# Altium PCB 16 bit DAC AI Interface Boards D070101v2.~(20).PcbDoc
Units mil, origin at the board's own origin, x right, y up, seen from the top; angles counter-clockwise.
Board outline 2600 x 10000 mil, 4 copper layers (Top Layer, InternalPlane1, InternalPlane2, Bottom Layer); 6 components, 34 nets, 183 pads, 15 vias.
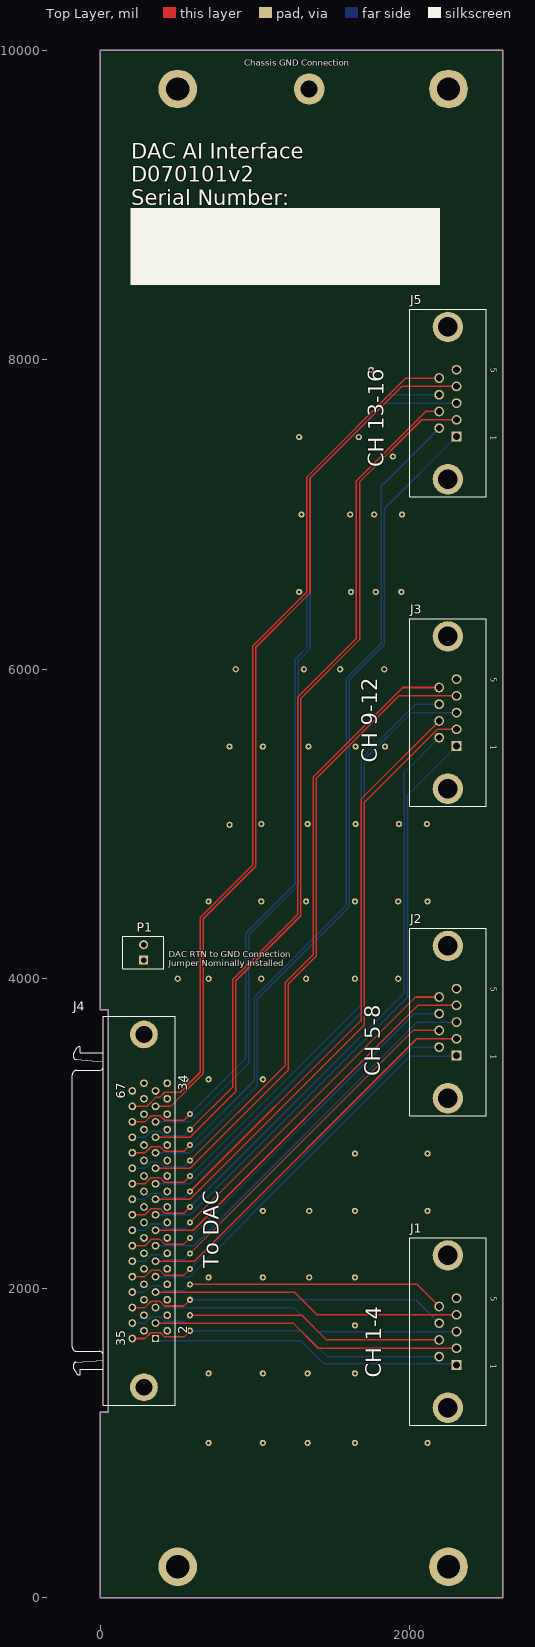
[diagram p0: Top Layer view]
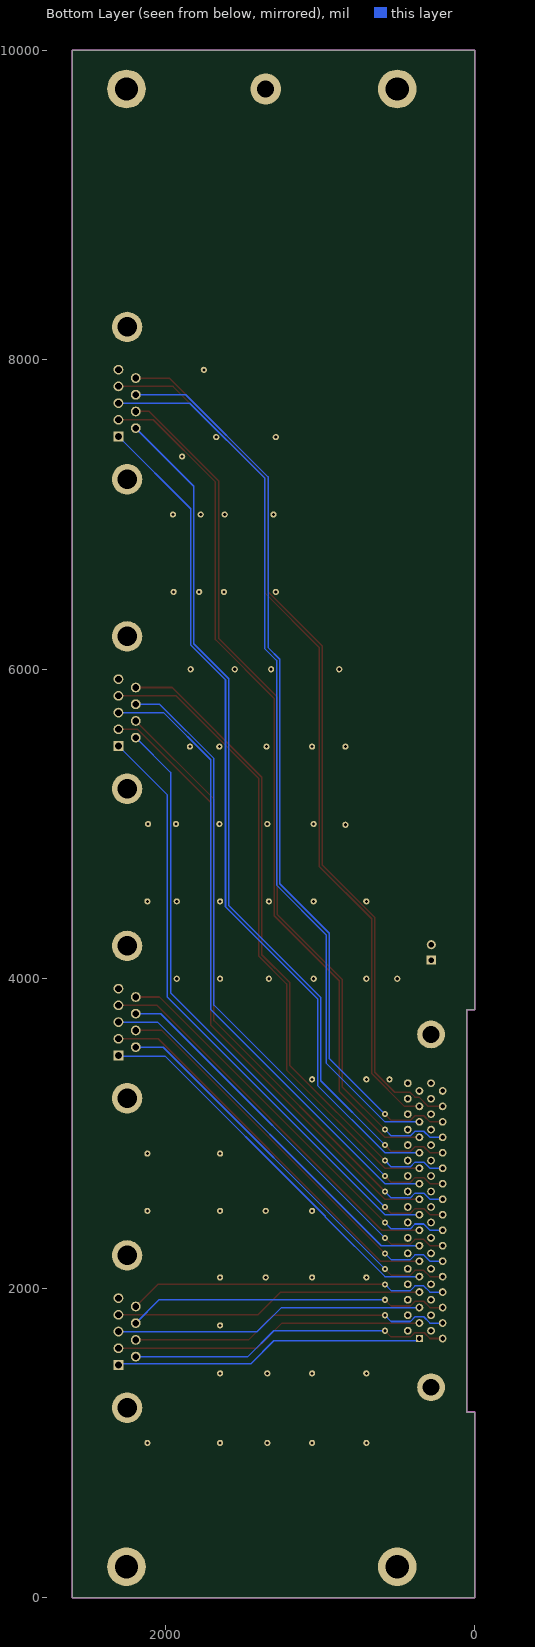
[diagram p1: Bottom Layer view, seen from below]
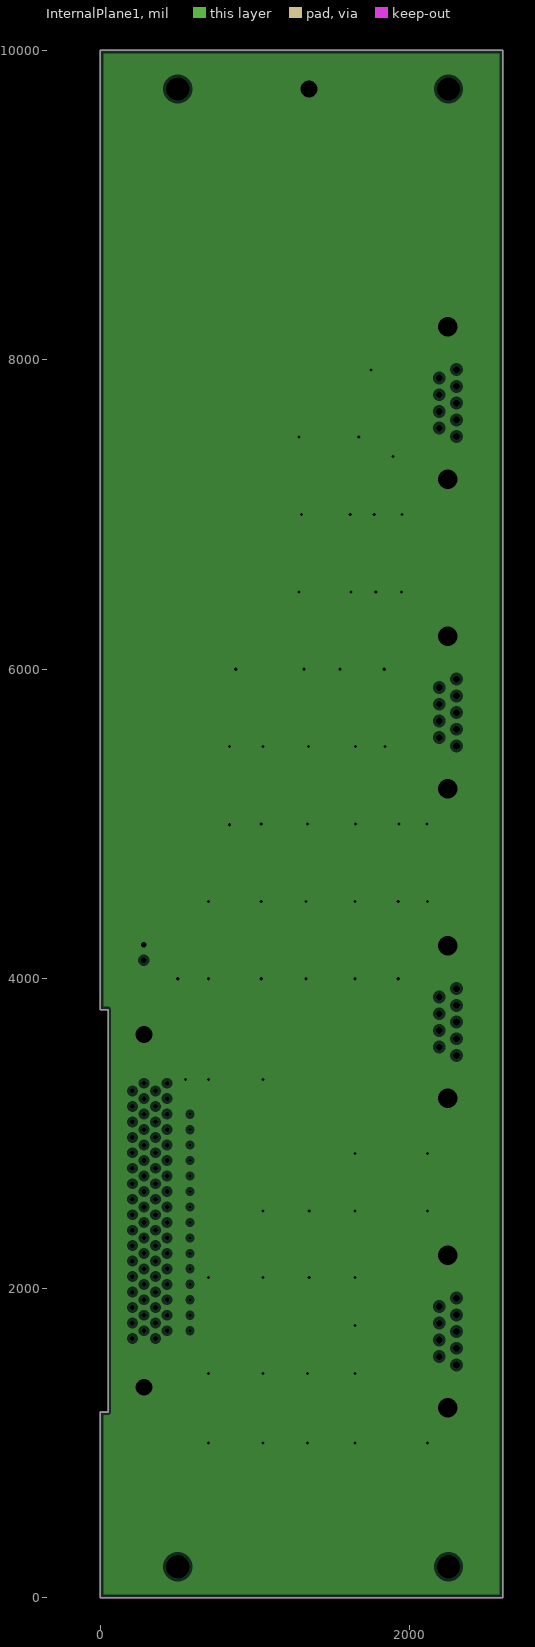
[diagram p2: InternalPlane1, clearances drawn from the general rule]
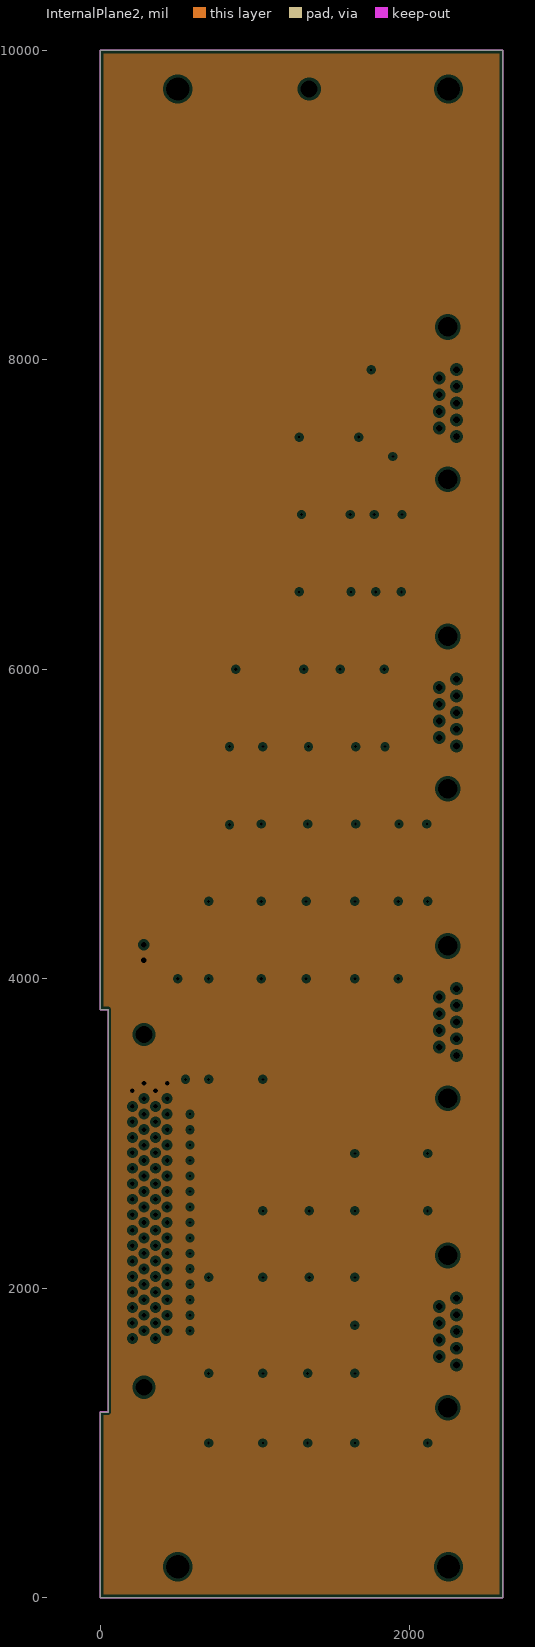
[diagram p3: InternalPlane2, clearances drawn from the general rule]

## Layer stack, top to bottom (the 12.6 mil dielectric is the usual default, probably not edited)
Top Solder: solder mask 0.4, Solder Resist, Dk 3.5
Top Layer: signal copper 1.4
Dielectric1: core 12.6, FR-4, Dk 4.8
InternalPlane1: plane copper 1.4, net GND
Dielectric2: prepreg 12.6, FR-4, Dk 4.8
InternalPlane2: plane copper 1.4, net INPUTRTN
Dielectric3: core 12.6, FR-4, Dk 4.8
Bottom Layer: signal copper 1.4
Bottom Solder: solder mask 0.4, Solder Resist, Dk 3.5

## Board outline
0,0 0,1200 50,1200 50,3800 0,3800 0,10000 2600,10000 2600,0

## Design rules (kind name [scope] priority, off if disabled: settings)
Clearance [All] p1: gap=10 ignorepadtopadclearanceinfootprint=FALSE except(0: Arc-Hole Track-Hole SMDPad-Hole THPad-Hole Via-Hole Fill-Hole Poly-Hole Region-Hole Text-Hole)
FabricationTestPointUsage TestPointUsage [All] p1: valid=0 allowmultiple=FALSE
FabricationTestpoint Testpoint [All] p1: side=3 testpointundercomponent=TRUE minsize=40 maxsize=100 preferedsize=60 minholesize=0 maxholesize=40 preferedholesize=32 testpointgrid=1 allowsidetop=TRUE allowsidebottom=TRUE usegrid=TRUE gridtolerance=0.01
HoleSize [All] p1: absolutevalues=TRUE maxlimit=200 minlimit=1 maxpercent=80.000 minpercent=20.000
PlaneClearance [All] p1: clearance=20
PlaneConnect [All] p1: planeconnectstyle=Relief reliefexpansion=20 reliefentries=4 reliefconductorwidth=10 reliefairgap=10
PolygonConnect [All] p1: connectstyle=Relief reliefconductorwidth=10 reliefentries=4 polygonreliefangle="90 Angle" airgapwidth=10
RoutingVias [All] p1: holewidth=20 width=40 viastyle="Through Hole" minholewidth=20 minwidth=40 maxholewidth=28 maxwidth=50
SolderMaskExpansion [All] p1: expansion=4
Width [All] p1: maxlimit=100 minlimit=10 preferedwidth=10
25 further rules are at their usual default settings.

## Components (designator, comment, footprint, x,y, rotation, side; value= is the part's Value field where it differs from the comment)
J1 "D9F" D9F 2246,1720 r270 top
J2 "D9F" D9F 2246,3720 r270 top
J3 "D9F" D9F 2246,5720 r270 top
J4 "787082-7" 787082-7 20,2500 r90 top
J5 "D9F" D9F 2246,7720 r270 top
P1 "Header 2" HDR1X2 280,4120 r90 top

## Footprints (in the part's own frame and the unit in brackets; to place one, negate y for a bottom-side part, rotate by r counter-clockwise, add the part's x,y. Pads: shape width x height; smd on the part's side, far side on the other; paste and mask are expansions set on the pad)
787082-7 [mm] "Connector; D Subminiature 050 Series; 68 Position; Right Angle"
  rect 1.143x1.143 hole 0.762: 1(-20.955,-8.555)
  round 1.27 hole 0.762: 2(-19.685,-10.46) 3(-18.415,-8.555) 4(-17.145,-10.46) 5(-15.875,-8.555) 6(-14.605,-10.46) 7(-13.335,-8.555) 8(-12.065,-10.46) 9(-10.795,-8.555) 10(-9.525,-10.46) 11(-8.255,-8.555) 12(-6.985,-10.46) 13(-5.715,-8.555) 14(-4.445,-10.46) 15(-3.175,-8.555) 16(-1.905,-10.46) 17(-0.635,-8.555) 18(0.635,-10.46) 19(1.905,-8.555) 20(3.175,-10.46) 21(4.445,-8.555) 22(5.715,-10.46) 23(6.985,-8.555) 24(8.255,-10.46) 25(9.525,-8.555) 26(10.795,-10.46) 27(12.065,-8.555) 28(13.335,-10.46) 29(14.605,-8.555) 30(15.875,-10.46) 31(17.145,-8.555) 32(18.415,-10.46) 33(19.685,-8.555) 34(20.955,-10.46) 35(-20.955,-4.745) 36(-19.685,-6.65) 37(-18.415,-4.745) 38(-17.145,-6.65) 39(-15.875,-4.745) 40(-14.605,-6.65) 41(-13.335,-4.745) 42(-12.065,-6.65) 43(-10.795,-4.745) 44(-9.525,-6.65) 45(-8.255,-4.745) 46(-6.985,-6.65) 47(-5.715,-4.745) 48(-4.445,-6.65) 49(-3.175,-4.745) 50(-1.905,-6.65) 51(-0.635,-4.745) 52(0.635,-6.65) 53(1.905,-4.745) 54(3.175,-6.65) 55(4.445,-4.745) 56(5.715,-6.65) 57(6.985,-4.745) 58(8.255,-6.65) 59(9.525,-4.745) 60(10.795,-6.65) 61(12.065,-4.745) 62(13.335,-6.65) 63(14.605,-4.745) 64(15.875,-6.65) 65(17.145,-4.745) 66(18.415,-6.65) 67(19.685,-4.745) 68(20.955,-6.65)
  round 4.55 hole 2.77: 69(-28.955,-6.65) 70(28.955,-6.65)
  silkscreen extent -31.95,-11.76 31.95,5.11, body extent -31.94,-11.8 31.94,5.07, height 9.49
D9F [mm]
  rect 1.6x1.6 hole 1.1: 1(5.486,1.422)
  round 1.6 hole 1.1: 2(2.743,1.422) 3(0.005,1.422) 4(-2.743,1.422) 5(-5.486,1.422) 6(4.115,-1.422) 7(1.372,-1.422) 8(-1.372,-1.422) 9(-4.115,-1.422)
  round 5 hole 3.2: 10(-12.497,0) 11(12.497,0)
  silkscreen extent -15.4,-6.3 15.4,6.3, body extent -15.4,-6.3 15.41,6.3, height 12.18
HDR1X2 [mm] "Connector; Header; 2 Position"
  rect 1.5x1.5 hole 0.9: 1(0,0)
  round 1.5 hole 0.9: 2(2.54,0)
  silkscreen extent -1.4,-3.3 3.94,3.43, body extent -1.19,-3.1 3.73,3.25, height 10.68

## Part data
J1 J2 J3 J5: "9 Position D-Sub Receptacle, Female Sockets Connector", Case/Package=Metal, Color=Black, Current Rating=6A, Flammability Rating="UL94 V-0", Manufacturer="TE Connectivity", Manufacturer Part Number=5747150-7, Max Operating Temperature=105°C, Max Supply Voltage (AC)=250V, Max Voltage Rating (DC)=250.25kV, Min Operating Temperature=-55°C, Package Quantity=17, Supplier Part Number 1=A34073-ND, Voltage Rating=125V
J4: library part "D68F 90deg", "68 Position D-Type Receptacle, Female Sockets Connector", Color=Black, Current Rating=1A, Flammability Rating="UL94 V-0", Manufacturer="TE Connectivity", Manufacturer Part Number=7870827, Max Operating Temperature=105°C, Min Operating Temperature=-55°C, Package Quantity=8, Supplier Part Number 1=A3321-ND, Voltage Rating=30V
P1: "Connector Header Through Hole 2 position 0.100\" (2.54mm)", Color=White, Contact Resistance=10mR, Current Rating=4A, Flammability Rating="UL94 V-0", Insulation Resistance=500GR, Manufacturer=Molex, Manufacturer Part Number=22-23-2021, Max Operating Temperature=75°C, Min Operating Temperature=0°C, Package Quantity=3000, Supplier Part Number 1=WM4200-ND, Voltage Rating=250V

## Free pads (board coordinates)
  round 200 hole 110: 0(1350,9750)
  round 250 hole 150: 0(2250,200) 1(2250,9750) 2(500,9750) 3(500,200)
  round 40 hole 20: 5(1645,1450) 6(2115,1000) 7(1645,1760) 8(1645,1000) 9(700,1450) 10(1050,2070) 11(1645,2070) 12(1050,1000) 13(700,1000) 14(1050,2500) 15(1645,2500) 16(2115,2870) 21(1050,3350) 22(1350,2500) 23(700,3350) 24(700,2070) 25(550,3350) 26(700,4000) 27(1040,4000) 28(1330,4000) 29(1645,4000) 30(1925,4000) 32(1645,2870) 36(1340,1000) 36(1340,1450) 36(1350,2070) 37(1040,4500) 38(1330,4500) 39(1645,4500) 40(1925,4500) 41(1930,5000) 42(1650,5000) 43(1340,5000) 44(1040,5000) 45(835,4995) 46(700,4500) 47(500,4000) 48(835,5500) 49(1050,5500) 50(1345,5500) 51(1650,5500) 52(1840,5500) 53(1835,6000) 54(1550,6000) 55(1315,6000) 56(875,6000) 57(1620,6500) 58(1780,6500) 59(1945,6500) 60(1285,6500) 61(1300,7000) 62(1615,7000) 63(1770,7000) 64(1950,7000) 65(1890,7375) 66(1670,7500) 67(1285,7500) 68(1750,7935) 69(2115,4500) 70(2110,5000) 71(2115,2500) 75(1050,1450)

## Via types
v1: diameter 40, hole 20, Top Layer to Bottom Layer, 15 vias

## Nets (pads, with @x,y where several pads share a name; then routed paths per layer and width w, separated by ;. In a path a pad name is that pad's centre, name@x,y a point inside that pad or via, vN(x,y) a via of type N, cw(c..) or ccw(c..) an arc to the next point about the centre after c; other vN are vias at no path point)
GND: J1.10 J1.11 J2.10 J2.11 J3.10 J3.11 J4.69 J4.70 J5.10 J5.11 P1.2 pad.0@1350,9750 pad.5 pad.6 pad.7 pad.8 pad.9 pad.10 pad.11 pad.12 pad.13 pad.14 pad.15 pad.16 pad.21 pad.22 pad.23 pad.24 pad.25 pad.26 pad.27 pad.28 pad.29 pad.30 pad.32 pad.36 pad.37 pad.38 pad.39 pad.40 pad.41 pad.42 pad.43 pad.44 pad.45 pad.46 pad.47 pad.48 pad.49 pad.50 pad.51 pad.52 pad.53 pad.54 pad.55 pad.56 pad.57 pad.58 pad.59 pad.60 pad.61 pad.62 pad.63 pad.64 pad.65 pad.66 pad.67 pad.68 pad.69 pad.70 pad.71 pad.75
INPUTN1: J1.6 J4.35 | length 2097.1
  Top Layer w10: J4.35 288.38,1675 325.88,1712.5 387.74,1712.5 415.24,1685 540,1685 v1(580,1725)
  Bottom Layer w10: v1(580,1725) 1298.39,1725 1465.39,1558 2187,1558 J1.6@2190,1555
INPUTN2: J1.7 J4.37 | length 2095.4
  Top Layer w10: v1(580,1825) 1302.39,1825 1461.39,1666 2188,1666 J1.7@2190,1664
  Bottom Layer w10: J4.37 288.38,1775 328.38,1815 385.24,1815 415.24,1785 540,1785 v1(580,1825)
INPUTN3: J1.8 J4.39 | length 2091.3
  Top Layer w10: J4.39 288.38,1875 328.38,1915 385.24,1915 415.24,1885 540,1885 v1(580,1925)
  Bottom Layer w10: v1(580,1925) 2039,1925 J1.8
INPUTN4: J1.9 J4.41 | length 2088
  Top Layer w10: v1(580,2025) 2047,2025 J1.9
  Bottom Layer w10: J4.41 288.38,1975 328.38,2015 385.24,2015 415.24,1985 540,1985 v1(580,2025)
INPUTN5: J2.6 J4.43 | length 2623.6
  Top Layer w10: J4.43 288.38,2075 328.38,2115 385.24,2115 415.24,2085 540,2085 v1(580,2125)
  Bottom Layer w10: v1(580,2125) 2013,3558 2187,3558 J2.6@2190,3555
INPUTN6: J2.7 J4.45 | length 2626.5
  Top Layer w10: v1(580,2225) 2021,3666 2188,3666 J2.7@2190,3664
  Bottom Layer w10: J4.45 288.38,2175 328.38,2215 385.24,2215 415.24,2185 540,2185 v1(580,2225)
INPUTN7: J2.8 J4.47 | length 2629.4
  Top Layer w10: J4.47 288.38,2275 328.38,2315 385.24,2315 415.24,2285 540,2285 v1(580,2325)
  Bottom Layer w10: v1(580,2325) 2029,3774 2189,3774 J2.8@2190,3773
INPUTN8: J2.9 J4.49 | length 2632.3
  Top Layer w10: v1(580,2425) 2037,3882 J2.9
  Bottom Layer w10: J4.49 288.38,2375 328.38,2415 385.24,2415 415.24,2385 540,2385 v1(580,2425)
INPUTN9: J3.6 J4.51 | length 4123.3
  Top Layer w10: J4.51 288.38,2475 328.38,2515 385.24,2515 415.24,2485 540,2485 575,2520 v1@585,2520
  Bottom Layer w10: v1@585,2520 585,2530 1965,3910 1965,5333 2187,5555 J3.6@2190,5555
  other v1: 580,2525
INPUTN10: J3.7 J4.53 | length 4128.2
  Top Layer w10: v1@581,2622 581,2626 1685,3730 1685,5161 2188,5664 J3.7@2190,5664
  Bottom Layer w10: J4.53 288.38,2575 328.38,2615 385.24,2615 415.24,2585 540,2585 577,2622 v1@581,2622
  other v1: 580,2625
INPUTN11: J3.8 J4.55 | length 4228.1
  Top Layer w10: J4.55 288.38,2675 328.38,2715 385.24,2715 415.24,2685 540,2685 575,2720 v1@580,2720
  Bottom Layer w10: v1@580,2720 v1(580,2725) 1685,3830 1685,5422.78 2036.22,5774 2189,5774 J3.8@2190,5773
INPUTN12: J3.9 J4.57 | length 4283.7
  Top Layer w10: v1@580,2820 v1(580,2825) 1195,3440 1195,3975 1375,4155 1375,5302.78 1954.22,5882 J3.9
  Bottom Layer w10: J4.57 288.38,2775 328.38,2815 385.24,2815 415.24,2785 540,2785 575,2820 v1@580,2820
INPUTN13: J4.59 J5.6 | length 5718.6
  Top Layer w10: J4.59 288.38,2875 328.38,2915 385.24,2915 415.24,2885 540,2885 v1@575,2920
  Bottom Layer w10: v1@575,2920 v1(580,2925) 995,3340 995,3879.28 1589,4473.28 1589,5939 1815,6165 1815,7183 J5.6
INPUTN14: J4.61 J5.7 | length 5779
  Top Layer w10: v1(580,3025) 855,3300 855,3995 1275,4415 1275,5820 1655,6200 1655,7217.78 2103.22,7666 2188,7666 J5.7@2190,7664
  Bottom Layer w10: J4.61 288.38,2975 328.38,3015 385.24,3015 415.24,2985 540,2985 570.2,3015.2 v1@570.2,3029.8
INPUTN15: J4.63 J5.8 | length 5903.5
  Top Layer w10: J4.63 288.38,3075 328.38,3115 385.24,3115 415.24,3085 540,3085 v1(580,3125)
  Bottom Layer w10: 595,3140 940,3485 940,4293.28 1260,4613.28 1260,6065 1335,6140 1335,7242.78 1866.22,7774 2189,7774 J5.8@2190,7773
INPUTN16: J4.65 J5.9 | length 5782.4
  Top Layer w10: J4.65 300.24,3175 360.24,3235 385.24,3235 416.82,3266.58 516.08,3266.58 645,3395.5 645,4395.5 985,4735.5 985,6150.5 1335,6500.5 1335,7242.78 1974.22,7882 J5.9
INPUTP1: J1.1 J4.1 | length 2016
  Bottom Layer w10: J4.1 371.81,1660 1297.5,1660 1445.99,1511.5 2294.5,1511.5 J1.1
INPUTP2: J1.2 J4.3 | length 2011.9
  Top Layer w10: J4.3 1244.83,1775 1407.83,1612 2297,1612 J1.2@2300,1609
INPUTP3: J1.3 J4.5 | length 2008.2
  Bottom Layer w10: J4.5 1248.83,1875 1404.03,1719.8 2298.2,1719.8 J1.3@2300,1718
INPUTP4: J1.4 J4.7 | length 2004.5
  Top Layer w10: J4.7 1252.83,1975 1399.83,1828 2299,1828 J1.4@2300,1827
INPUTP5: J2.1 J4.9 | length 2535.8
  Bottom Layer w10: J4.9 579.5,2075 965,2460.5 965,2464.5 2000.5,3500 J2.1@2300,3500
INPUTP6: J2.2 J4.11 | length 2539.7
  Top Layer w10: J4.11 607.83,2175 2044.83,3612 2297,3612 J2.2@2300,3609
INPUTP7: J2.3 J4.13 | length 2543.6
  Bottom Layer w10: J4.13 603.83,2275 2048.63,3719.8 J2.3
INPUTP8: J2.4 J4.15 | length 2547
  Top Layer w10: J4.15 599.83,2375 2052.83,3828 J2.4
INPUTP9: J3.1 J4.17 | length 3965.2
  Bottom Layer w10: J4.17 579.5,2475 1985,3880.5 1985,5187 J3.1
INPUTP10: J3.2 J4.19 | length 4044.9
  Top Layer w10: J4.19 579.5,2575 1705,3700.5 1705,5138.76 2178.24,5612 2297,5612 J3.2@2300,5609
INPUTP11: J3.3 J4.21 | length 4150.6
  Bottom Layer w10: J4.21 579.5,2675 1705,3800.5 1705,5414.5 2010.31,5719.8 2298.2,5719.8 J3.3@2300,5718
INPUTP12: J3.4 J4.23 | length 4206.4
  Top Layer w10: J4.23 579.5,2775 1215,3410.5 1215,3966.72 1395,4146.72 1395,5294.5 1928.5,5828 2299,5828 J3.4@2300,5827
INPUTP13: J4.25 J5.1 | length 5565.2
  Bottom Layer w10: J4.25 579.5,2875 1015,3310.5 1015,3871 1610,4466 1610,5931.72 1835,6156.72 1835,7037 J5.1
INPUTP14: J4.27 J5.2 | length 5703.9
  Top Layer w10: J4.27 579.5,2975 875,3270.5 875,3986.72 1295,4406.72 1295,5811.72 1675,6191.72 1675,7209.5 2077.5,7612 2297,7612 J5.2@2300,7609
INPUTP15: J4.29 J5.3 | length 5852.2
  Bottom Layer w10: J4.29 579.5,3075 960,3455.5 960,4285 1280,4605 1280,6056.72 1355,6131.72 1355,7234.5 1840.31,7719.8 2300.2,7719.8 J5.3@2302,7718
INPUTP16: J4.31 J5.4 | length 5720.4
  Top Layer w10: J4.31 452.78,3175 665,3387.22 665,4387.22 1005,4727.22 1005,6142.22 1355,6492.22 1355,7234.5 1948.5,7828 2299,7828 J5.4@2300,7827
INPUTRTN: J4.33 J4.34 J4.67 J4.68 P1.1
pads on no net: J1.5 J2.5 J3.5 J4.2 J4.4 J4.6 J4.8 J4.10 J4.12 J4.14 J4.16 J4.18 J4.20 J4.22 J4.24 J4.26 J4.28 J4.30 J4.32 J4.36 J4.38 J4.40 J4.42 J4.44 J4.46 J4.48 J4.50 J4.52 J4.54 J4.56 J4.58 J4.60 J4.62 J4.64 J4.66 J5.5

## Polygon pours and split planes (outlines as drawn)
GND on InternalPlane1 (split plane): 2579.9,20.1 20.1,20.1 20.1,1179.9 50,1179.9 53.92,1180.29 57.69,1181.43 61.17,1183.29 64.21,1185.79 66.71,1188.83 68.57,1192.31 69.71,1196.08 70.1,1200 70.1,3800 69.71,3803.92 68.57,3807.69 66.71,3811.17 64.21,3814.21 61.17,3816.71 57.69,3818.57 53.92,3819.71 50,3820.1 20.1,3820.1 20.1,9979.9 2579.9,9979.9
INPUTRTN on InternalPlane2 (split plane): 2579.9,20.1 20.1,20.1 20.1,1179.9 50,1179.9 53.92,1180.29 57.69,1181.43 61.17,1183.29 64.21,1185.79 66.71,1188.83 68.57,1192.31 69.71,1196.08 70.1,1200 70.1,3800 69.71,3803.92 68.57,3807.69 66.71,3811.17 64.21,3814.21 61.17,3816.71 57.69,3818.57 53.92,3819.71 50,3820.1 20.1,3820.1 20.1,9979.9 2579.9,9979.9

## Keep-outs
Keep-Out Layer:
  the board outline again, w10

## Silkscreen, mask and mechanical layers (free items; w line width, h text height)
Top Overlay:
  rectangle: 194,8482 2194,8982
  text "Chassis GND Connection" at 930,9900 h40
  text "DAC AI Interface / D070101v2 / Serial Number:" at 200,9000 h100
  text "CH 13-16" at 1830,7305 h100 r90
  text "CH 9-12" at 1790,5395 h100 r90
  text "DAC RTN to GND Connection / Jumper Nominally Installed" at 441,4080 h40
  text "CH 5-8" at 1810,3370 h100 r90
  text "To DAC" at 765,2130 h100 r90
  text "CH 1-4" at 1815,1420 h100 r90
Mechanical 1:
  lines w10: 0,0 0,1200 50,1200 50,2500 50,3800 0,3800 0,10000 2600,10000 2600,0 0,0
